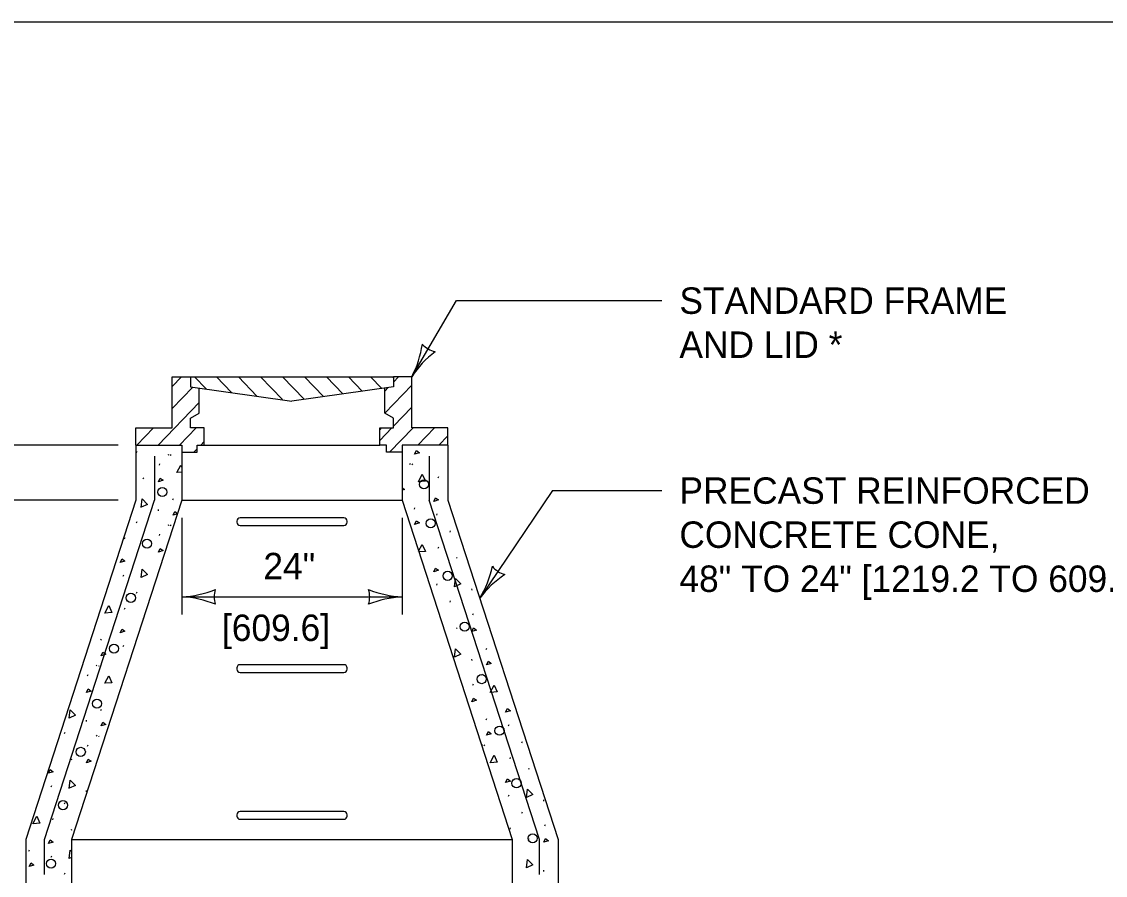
# Model space of a CAD drawing. Extents: x 49991.4 to 50028.3, y 49987.6 to 50011.4.
# Drawn here: x 50007.274 to 50009.735, y 49997.062 to 49998.999 of the extents above; entities that cross this region are included whole.
import ezdxf

# ---------------------------------------------------------------- set-up
doc = ezdxf.new("R2010")
doc.units = 0
for name, color, linetype in [('Level 1', 7, 'Continuous'), ('Level 2', 7, 'Continuous'), ('Level 3', 7, 'Continuous')]:
    doc.layers.add(name, color=color, linetype=linetype)

msp = doc.modelspace()

# ---------------------------------------------------------------- linework, layer by layer
at = {"layer": 'Level 1'}
for p, q in [((50007.6159, 49998.0775), (50007.6159, 49998.1931)), ((50007.6159, 49998.1931), (50007.6576, 49998.1931)), ((50007.6372, 49998.1931), (50007.6159, 49998.171)), ((50007.6576, 49998.1931), (50007.6576, 49998.1707)), ((50007.6576, 49998.1931), (50008.1183, 49998.1931)), ((50007.6666, 49998.1931), (50007.693, 49998.1658)), ((50007.7166, 49998.1931), (50007.7508, 49998.1576)), ((50007.7666, 49998.1931), (50007.8086, 49998.1495)), ((50007.8166, 49998.1931), (50007.8665, 49998.1414)), ((50007.8666, 49998.1931), (50007.9157, 49998.1422)), ((50007.9166, 49998.1931), (50007.9597, 49998.1484)), ((50007.9666, 49998.1931), (50008.0037, 49998.1546)), ((50008.0166, 49998.1931), (50008.0477, 49998.1608)), ((50008.0666, 49998.1931), (50008.0918, 49998.167)), ((50008.1166, 49998.1931), (50008.1183, 49998.1913)), ((50008.16, 49998.1931), (50008.1183, 49998.1931)), ((50008.1183, 49998.1931), (50008.1183, 49998.1707)), ((50008.13, 49998.1931), (50008.1183, 49998.181)), ((50008.16, 49998.0775), (50008.16, 49998.1931)), ((50007.6632, 49998.1699), (50007.6159, 49998.121)), ((50007.6576, 49998.1707), (50007.888, 49998.1383)), ((50007.6773, 49998.1106), (50007.6773, 49998.168)), ((50008.1183, 49998.1707), (50007.888, 49998.1383)), ((50008.16, 49998.1743), (50008.0986, 49998.1106)), ((50008.1068, 49998.1691), (50008.0986, 49998.1606)), ((50008.0986, 49998.1106), (50008.0986, 49998.168)), ((50007.6773, 49998.1346), (50007.5844, 49998.0383)), ((50008.16, 49998.1243), (50008.1183, 49998.081)), ((50007.6576, 49998.0992), (50007.6773, 49998.1106)), ((50007.6576, 49998.0775), (50007.6576, 49998.0992)), ((50008.1183, 49998.0992), (50008.0986, 49998.1106)), ((50008.1183, 49998.0775), (50008.1183, 49998.0992)), ((50007.5338, 49998.0383), (50007.5338, 49998.0775)), ((50007.5338, 49998.0775), (50007.6159, 49998.0775)), ((50007.574, 49998.0775), (50007.5362, 49998.0383)), ((50007.6704, 49998.0775), (50007.6327, 49998.0383)), ((50007.6885, 49998.0775), (50007.6576, 49998.0775)), ((50007.6885, 49998.0383), (50007.6885, 49998.0775)), ((50008.0874, 49998.0383), (50008.0874, 49998.0775)), ((50008.0874, 49998.0775), (50008.1183, 49998.0775)), ((50008.0908, 49998.0775), (50008.0874, 49998.074)), ((50008.1149, 49998.0775), (50008.0874, 49998.049)), ((50008.1632, 49998.0775), (50008.1096, 49998.022)), ((50008.2422, 49998.0775), (50008.16, 49998.0775)), ((50008.2114, 49998.0775), (50008.1736, 49998.0383)), ((50008.2422, 49998.0383), (50008.2422, 49998.0775)), ((50007.6885, 49998.0462), (50007.6809, 49998.0383)), ((50008.2422, 49998.0594), (50008.2218, 49998.0383)), ((50007.5338, 49998.0383), (50007.5338, 49997.9133)), ((50007.5338, 49998.0383), (50007.638, 49998.0383)), ((50007.5351, 49998.0213), (50007.5364, 49998.0243)), ((50007.6067, 49998.0174), (50007.608, 49998.0154)), ((50007.6118, 49998.0166), (50007.6131, 49998.0146)), ((50007.638, 49998.0383), (50007.638, 49997.9133)), ((50007.638, 49998.022), (50007.673, 49998.022)), ((50007.673, 49998.0301), (50007.6651, 49998.022)), ((50007.673, 49998.022), (50007.673, 49998.0383)), ((50007.673, 49998.0383), (50007.6885, 49998.0383)), ((50007.6885, 49998.0383), (50008.0874, 49998.0383)), ((50008.103, 49998.0383), (50008.0874, 49998.0383)), ((50008.103, 49998.022), (50008.103, 49998.0383)), ((50008.138, 49998.022), (50008.103, 49998.022)), ((50008.2422, 49998.0383), (50008.138, 49998.0383)), ((50008.138, 49998.0383), (50008.138, 49997.9133)), ((50008.2422, 49998.0383), (50008.2422, 49997.9133)), ((50007.5762, 49998.0133), (50007.5762, 49997.9133)), ((50007.587, 49997.9927), (50007.5884, 49997.9957)), ((50008.1552, 49997.9965), (50008.1566, 49997.9945)), ((50008.1603, 49997.9958), (50008.1616, 49997.9938)), ((50008.1998, 49998.0133), (50008.1998, 49997.9133)), ((50008.2199, 49997.9642), (50008.2212, 49997.9672)), ((50007.5497, 49997.9637), (50007.551, 49997.9617)), ((50007.6174, 49997.9141), (50007.6188, 49997.9171)), ((50007.5338, 49997.9133), (50007.2835, 49997.143)), ((50007.3259, 49997.143), (50007.5762, 49997.9133)), ((50007.638, 49997.9133), (50007.3877, 49997.143)), ((50007.584, 49997.8921), (50007.5843, 49997.8891)), ((50007.638, 49997.9133), (50008.138, 49997.9133)), ((50008.138, 49997.9133), (50008.3883, 49997.143)), ((50008.166, 49997.8932), (50008.1673, 49997.8962)), ((50008.4501, 49997.143), (50008.1998, 49997.9133)), ((50008.2422, 49997.9133), (50008.4924, 49997.143)), ((50008.0056, 49997.8732), (50007.7704, 49997.8732)), ((50008.2166, 49997.8796), (50008.2179, 49997.8826)), ((50007.5351, 49997.8618), (50007.5364, 49997.8648)), ((50007.6067, 49997.8579), (50007.608, 49997.8559)), ((50007.6118, 49997.8572), (50007.6131, 49997.8552)), ((50007.763, 49997.8658), (50007.763, 49997.8632)), ((50007.7704, 49997.8557), (50008.0056, 49997.8557)), ((50008.013, 49997.8632), (50008.013, 49997.8658)), ((50008.2469, 49997.841), (50008.2482, 49997.844)), ((50007.5081, 49997.8256), (50007.5094, 49997.8286)), ((50007.587, 49997.8332), (50007.5884, 49997.8362)), ((50008.2199, 49997.8047), (50008.2212, 49997.8077)), ((50008.2615, 49997.7834), (50008.2629, 49997.7814)), ((50007.5048, 49997.741), (50007.5061, 49997.744)), ((50008.2166, 49997.7201), (50008.2179, 49997.7231)), ((50007.5351, 49997.7024), (50007.5364, 49997.7054)), ((50008.2958, 49997.7118), (50008.2961, 49997.7088)), ((50008.2469, 49997.6815), (50008.2482, 49997.6845)), ((50008.3185, 49997.6776), (50008.319, 49997.6769)), ((50007.5081, 49997.6661), (50007.5094, 49997.6691)), ((50008.2988, 49997.6529), (50008.3002, 49997.6559)), ((50007.5497, 49997.6448), (50007.5504, 49997.6438)), ((50008.2615, 49997.6239), (50008.2629, 49997.6219)), ((50007.4542, 49997.5952), (50007.4555, 49997.5982)), ((50007.5048, 49997.5815), (50007.5061, 49997.5845)), ((50008.3292, 49997.5743), (50008.3306, 49997.5773)), ((50008.2958, 49997.5523), (50008.2961, 49997.5493)), ((50007.4434, 49997.539), (50007.4447, 49997.537)), ((50007.4485, 49997.5382), (50007.4498, 49997.5362)), ((50007.763, 49997.5325), (50007.763, 49997.5298)), ((50008.0056, 49997.5399), (50007.7704, 49997.5399)), ((50007.7704, 49997.5224), (50008.0056, 49997.5224)), ((50008.013, 49997.5298), (50008.013, 49997.5325)), ((50007.4238, 49997.5143), (50007.4251, 49997.5173)), ((50008.3185, 49997.5181), (50008.3198, 49997.5161)), ((50008.2988, 49997.4934), (50008.3002, 49997.4964)), ((50007.4542, 49997.4357), (50007.4555, 49997.4387)), ((50007.4207, 49997.4137), (50007.421, 49997.4107)), ((50008.3292, 49997.4148), (50008.3306, 49997.4178)), ((50008.3798, 49997.4012), (50008.3812, 49997.4042)), ((50007.3718, 49997.3834), (50007.3731, 49997.3864)), ((50007.4434, 49997.3796), (50007.4447, 49997.3776)), ((50007.4485, 49997.3788), (50007.4498, 49997.3768)), ((50007.4238, 49997.3549), (50007.4251, 49997.3579)), ((50008.3185, 49997.3587), (50008.3198, 49997.3567)), ((50008.3236, 49997.3579), (50008.3249, 49997.3559)), ((50008.4102, 49997.3626), (50008.4115, 49997.3656)), ((50007.3864, 49997.3259), (50007.3878, 49997.3239)), ((50008.3832, 49997.3263), (50008.3845, 49997.3293)), ((50008.4248, 49997.305), (50008.4261, 49997.303)), ((50007.3415, 49997.2626), (50007.3428, 49997.2656)), ((50007.4207, 49997.2542), (50007.421, 49997.2513)), ((50007.3718, 49997.224), (50007.3731, 49997.227)), ((50008.3798, 49997.2418), (50008.3812, 49997.2448)), ((50008.459, 49997.2334), (50008.4594, 49997.2304)), ((50008.0056, 49997.2066), (50007.7704, 49997.2066)), ((50008.4102, 49997.2031), (50008.4115, 49997.2061)), ((50007.3448, 49997.1878), (50007.3462, 49997.1908)), ((50007.763, 49997.1992), (50007.763, 49997.1965)), ((50007.7704, 49997.1891), (50008.0056, 49997.1891)), ((50008.013, 49997.1965), (50008.013, 49997.1992)), ((50008.4621, 49997.1745), (50008.4634, 49997.1775)), ((50007.3864, 49997.1664), (50007.3878, 49997.1644)), ((50008.3832, 49997.1669), (50008.3845, 49997.1699)), ((50007.2835, 49997.143), (50007.2835, 49995.7888)), ((50007.3259, 49997.0638), (50007.3259, 49997.143)), ((50007.3877, 49997.143), (50007.3877, 49995.2888)), ((50007.3877, 49997.143), (50008.3883, 49997.143)), ((50008.3883, 49997.143), (50008.3883, 49995.2888)), ((50008.4248, 49997.1456), (50008.4261, 49997.1436)), ((50008.4501, 49997.0638), (50008.4501, 49997.143)), ((50008.4924, 49997.143), (50008.4924, 49995.7888)), ((50007.2909, 49997.1168), (50007.2922, 49997.1198)), ((50007.3415, 49997.1032), (50007.3428, 49997.1062)), ((50007.3718, 49997.0646), (50007.3731, 49997.0676)), ((50008.459, 49997.0739), (50008.4594, 49997.0709))]:
    msp.add_line(p, q, dxfattribs=at)
msp.add_lwpolyline([(49999.3835, 49998.9992), (50016.7501, 49998.9992), (50016.7501, 49987.7988), (49999.3835, 49987.7988)], close=True, dxfattribs=at)
for points in [[(50008.1666, 49998.0177), (50008.1706, 49998.026), (50008.1773, 49998.021), (50008.1666, 49998.0177)], [(50007.6264, 49997.976), (50007.6354, 49997.993), (50007.638, 49997.9873)], [(50007.638, 49997.977), (50007.6268, 49997.976)], [(50008.175, 49997.9552), (50008.184, 49997.9722), (50008.191, 49997.9565), (50008.1753, 49997.9552)], [(50007.5847, 49997.955), (50007.5887, 49997.9634), (50007.5954, 49997.9584), (50007.5847, 49997.955)], [(50008.138, 49997.942), (50008.1439, 49997.9375), (50008.138, 49997.9357)], [(50007.5453, 49997.897), (50007.5479, 49997.916), (50007.5598, 49997.9037), (50007.5456, 49997.8971)], [(50008.21, 49997.9104), (50008.214, 49997.9187), (50008.2206, 49997.9137), (50008.21, 49997.9104)], [(50007.6181, 49997.8791), (50007.6221, 49997.8874), (50007.6281, 49997.883)], [(50007.6279, 49997.8822), (50007.6181, 49997.8791)], [(50008.1666, 49997.8582), (50008.1706, 49997.8666), (50008.1773, 49997.8616), (50008.1666, 49997.8582)], [(50007.5847, 49997.7956), (50007.5887, 49997.8039), (50007.5954, 49997.7989), (50007.5847, 49997.7956)], [(50008.1757, 49997.7972), (50008.184, 49997.8127), (50008.191, 49997.797), (50008.1762, 49997.7958)], [(50007.4982, 49997.7718), (50007.5022, 49997.7801), (50007.5088, 49997.7751), (50007.4982, 49997.7718)], [(50007.5453, 49997.7376), (50007.5479, 49997.7566), (50007.5598, 49997.7443), (50007.5456, 49997.7376)], [(50008.21, 49997.7509), (50008.214, 49997.7592), (50008.2206, 49997.7542), (50008.21, 49997.7509)], [(50008.2571, 49997.7167), (50008.2597, 49997.7357), (50008.2716, 49997.7234), (50008.2574, 49997.7168)], [(50007.4632, 49997.6571), (50007.4721, 49997.6741), (50007.4791, 49997.6584), (50007.4635, 49997.6571)], [(50007.4982, 49997.6124), (50007.5022, 49997.6207), (50007.5088, 49997.6157), (50007.4982, 49997.6124)], [(50008.2965, 49997.6153), (50008.3005, 49997.6236), (50008.3072, 49997.6186), (50008.2965, 49997.6153)], [(50008.2571, 49997.5572), (50008.2597, 49997.5762), (50008.2716, 49997.5639), (50008.2574, 49997.5573)], [(50007.4548, 49997.5602), (50007.4588, 49997.5686), (50007.4655, 49997.5636), (50007.4548, 49997.5602)], [(50008.3299, 49997.5394), (50008.3339, 49997.5477), (50008.3406, 49997.5427), (50008.3299, 49997.5394)], [(50007.4632, 49997.4977), (50007.4721, 49997.5146), (50007.4791, 49997.499), (50007.4635, 49997.4977)], [(50007.4214, 49997.4767), (50007.4254, 49997.485), (50007.4321, 49997.48), (50007.4214, 49997.4767)], [(50008.3382, 49997.4768), (50008.3472, 49997.4938), (50008.3542, 49997.4781), (50008.3386, 49997.4768)], [(50008.2965, 49997.4558), (50008.3005, 49997.4642), (50008.3072, 49997.4592), (50008.2965, 49997.4558)], [(50007.382, 49997.4186), (50007.3846, 49997.4377), (50007.3966, 49997.4254), (50007.3823, 49997.4188)], [(50008.3732, 49997.432), (50008.3772, 49997.4404), (50008.3839, 49997.4354), (50008.3732, 49997.432)], [(50007.4548, 49997.4008), (50007.4588, 49997.4091), (50007.4655, 49997.4041), (50007.4548, 49997.4008)], [(50008.3299, 49997.3799), (50008.3339, 49997.3882), (50008.3406, 49997.3832), (50008.3299, 49997.3799)], [(50007.4214, 49997.3172), (50007.4254, 49997.3256), (50007.4321, 49997.3206), (50007.4214, 49997.3172)], [(50008.3382, 49997.3174), (50008.3472, 49997.3343), (50008.3542, 49997.3187), (50008.3386, 49997.3174)], [(50007.3349, 49997.2934), (50007.3389, 49997.3018), (50007.3456, 49997.2968), (50007.3349, 49997.2934)], [(50007.382, 49997.2592), (50007.3846, 49997.2782), (50007.3966, 49997.2659), (50007.3823, 49997.2593)], [(50008.3732, 49997.2726), (50008.3772, 49997.2809), (50008.3839, 49997.2759), (50008.3732, 49997.2726)], [(50008.4204, 49997.2383), (50008.423, 49997.2573), (50008.4349, 49997.245), (50008.4207, 49997.2384)], [(50007.2999, 49997.1788), (50007.3089, 49997.1958), (50007.3158, 49997.1801), (50007.3002, 49997.1788)], [(50007.3349, 49997.134), (50007.3389, 49997.1423), (50007.3456, 49997.1373), (50007.3349, 49997.134)], [(50008.4598, 49997.1369), (50008.4638, 49997.1452), (50008.4704, 49997.1402), (50008.4598, 49997.1369)], [(50007.382, 49997.0997), (50007.3846, 49997.1188), (50007.3877, 49997.1156)], [(50007.2916, 49997.0818), (50007.2956, 49997.0902), (50007.3022, 49997.0852), (50007.2916, 49997.0818)], [(50007.3877, 49997.1023), (50007.3823, 49997.0998)], [(50008.4204, 49997.0788), (50008.423, 49997.0979), (50008.4349, 49997.0856), (50008.4207, 49997.079)]]:
    msp.add_lwpolyline(points, dxfattribs=at)
for centre in [(50007.5937, 49997.9318), (50008.1877, 49997.9491), (50008.2031, 49997.8607), (50007.559, 49997.8146), (50008.2417, 49997.7416), (50007.5223, 49997.6917), (50008.2803, 49997.6263), (50007.4838, 49997.5764), (50008.3188, 49997.5072), (50007.4452, 49997.4515), (50008.3593, 49997.39), (50007.4085, 49997.342), (50008.3979, 49997.2709), (50007.368, 49997.221), (50008.4345, 49997.146), (50007.341, 49997.0884)]:
    msp.add_circle(centre, 0.0104, dxfattribs=at)
for centre, start, end in [((50007.7704, 49997.8658), 90, 180), ((50008.0056, 49997.8658), 0, 90), ((50007.7704, 49997.8632), 180, 270), ((50008.0056, 49997.8632), 270, 0), ((50007.7704, 49997.5325), 90, 180), ((50007.7704, 49997.5299), 180, 270), ((50008.0056, 49997.5325), 0, 90), ((50008.0056, 49997.5299), 270, 0), ((50007.7704, 49997.1992), 90, 180), ((50008.0056, 49997.1992), 0, 90), ((50007.7704, 49997.1965), 180, 270), ((50008.0056, 49997.1965), 270, 0)]:
    msp.add_arc(centre, 0.00742, start, end, dxfattribs=at)
at = {"layer": 'Level 3'}
for p, q in [((50008.16, 49998.1931), (50008.2616, 49998.3661)), ((50008.2616, 49998.3661), (50008.7277, 49998.3661)), ((50007.4938, 49998.0383), (50006.6251, 49998.0383)), ((50008.4795, 49997.935), (50008.3145, 49997.6907)), ((50008.4795, 49997.935), (50008.7277, 49997.935)), ((50007.4938, 49997.9133), (50007.1635, 49997.9133)), ((50007.638, 49997.8733), (50007.638, 49997.6537)), ((50008.138, 49997.8733), (50008.138, 49997.6537)), ((50007.638, 49997.6937), (50008.138, 49997.6937))]:
    msp.add_line(p, q, dxfattribs=at)
for centre, radius, start, end in [((50007.9535, 49998.3011), 0.233, 332.4023, 351.6522), ((50008.2249, 49998.3037), 0.0548, 221.7138, 257.4362), ((50008.3469, 49998.0727), 0.2223, 127.031, 147.2145), ((50008.1152, 49997.8114), 0.233, 328.7962, 348.0461), ((50008.4935, 49997.5588), 0.2223, 123.4249, 143.6084), ((50008.3863, 49997.797), 0.0548, 218.1077, 253.8301), ((50007.6265, 49997.9264), 0.233, 272.8273, 292.0772), ((50007.7662, 49997.6937), 0.0548, 162.1388, 197.8612), ((50008.1472, 49997.9159), 0.2223, 247.456, 267.6395), ((50008.0098, 49997.6937), 0.0548, 342.1388, 17.8612), ((50007.6289, 49997.4716), 0.2223, 67.456, 87.6395), ((50008.1495, 49997.461), 0.233, 92.8273, 112.0772)]:
    msp.add_arc(centre, radius, start, end, dxfattribs=at)

# ---------------------------------------------------------------- texts
at = {"layer": 'Level 2'}
for s, p in [('STANDARD FRAME', (50008.7677, 49998.3361)), ('AND LID *', (50008.7677, 49998.2361)), ('PRECAST REINFORCED', (50008.7677, 49997.905)), ('CONCRETE CONE,', (50008.7677, 49997.805)), ('24"', (50007.8231, 49997.7337)), ('48" TO 24" [1219.2 TO 609.6]', (50008.7677, 49997.705)), ('[609.6]', (50007.7291, 49997.5937))]:
    msp.add_text(s, height=0.06, dxfattribs=at).set_placement(p)

doc.saveas('drawing.dxf')
